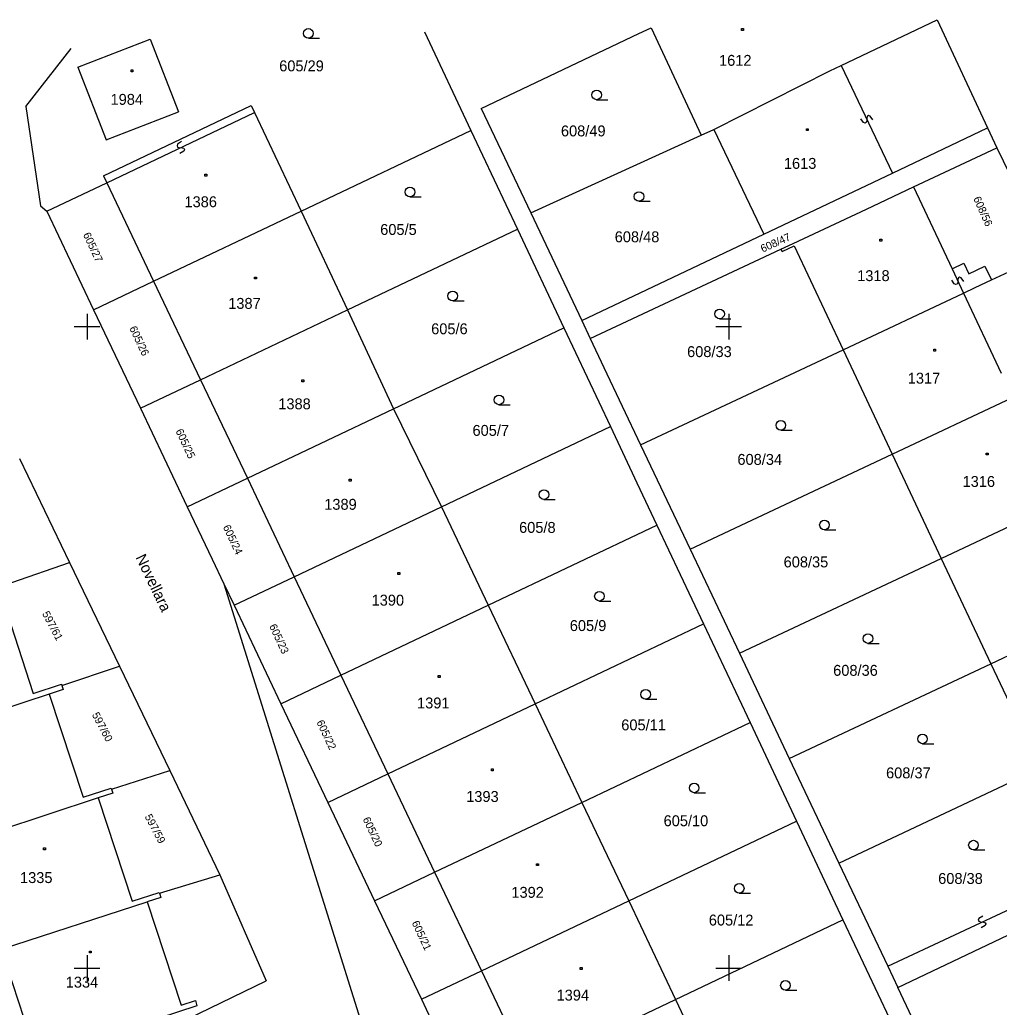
# Model space of a CAD drawing. Extents: x -493648 to -493033, y -1127718 to -1127026.
# Drawn here: x -493205.2 to -493128.9, y -1127103.1 to -1127026.1 of the extents above; entities that cross this region are included whole.
import ezdxf

# ---------------------------------------------------------------- set-up
doc = ezdxf.new("R2010")
doc.units = 0
doc.layers.add('katastrální mapa', color=7, linetype='Continuous')
doc.layers.add('síť', color=7, linetype='Continuous')

msp = doc.modelspace()

# ---------------------------------------------------------------- linework, layer by layer
at = {"layer": 'katastrální mapa'}
for p, q in [((-493141.24, -1127029.66), (-493133.78, -1127026.09)), ((-493133.78, -1127026.09), (-493129.84, -1127034.51)), ((-493157, -1127027.17), (-493156.05, -1127026.71)), ((-493156.05, -1127026.71), (-493152.15, -1127035.09)), ((-493149.02, -1127026.77), (-493148.87, -1127026.77)), ((-493149.02, -1127026.92), (-493149.02, -1127026.77)), ((-493148.87, -1127026.77), (-493148.87, -1127026.92)), ((-493200.73, -1127029.79), (-493195.09, -1127027.6)), ((-493195.09, -1127027.6), (-493192.87, -1127033.26)), ((-493182.76, -1127027.53), (-493181.88, -1127027.53)), ((-493173.71, -1127027.03), (-493170.09, -1127034.72)), ((-493169.29, -1127033.01), (-493157, -1127027.17)), ((-493148.87, -1127026.92), (-493149.02, -1127026.92)), ((-493204.77, -1127032.86), (-493201.25, -1127028.34)), ((-493200.73, -1127029.79), (-493198.5, -1127035.44)), ((-493142.14, -1127030.06), (-493141.24, -1127029.66)), ((-493141.24, -1127029.66), (-493137.26, -1127038.04)), ((-493196.57, -1127030), (-493196.42, -1127030)), ((-493196.57, -1127030.15), (-493196.57, -1127030)), ((-493196.42, -1127030.15), (-493196.57, -1127030.15)), ((-493196.42, -1127030), (-493196.42, -1127030.15)), ((-493151.17, -1127034.64), (-493142.14, -1127030.06)), ((-493204.77, -1127032.86), (-493203.62, -1127040.6)), ((-493198.72, -1127038.25), (-493187.21, -1127032.77)), ((-493187.21, -1127032.77), (-493186.95, -1127033.32)), ((-493169.29, -1127033.01), (-493165.43, -1127041.14)), ((-493160.3, -1127032.32), (-493159.42, -1127032.32)), ((-493198.5, -1127035.44), (-493192.87, -1127033.26)), ((-493198.46, -1127038.79), (-493186.95, -1127033.32)), ((-493186.95, -1127033.32), (-493183.32, -1127041.01)), ((-493139.2, -1127033.6), (-493139.25, -1127033.74)), ((-493139.25, -1127033.74), (-493139.25, -1127033.96)), ((-493139.11, -1127033.56), (-493139.2, -1127033.6)), ((-493138.98, -1127033.61), (-493139.11, -1127033.56)), ((-493138.78, -1127033.9), (-493138.98, -1127033.61)), ((-493139.52, -1127034.09), (-493139.72, -1127033.8)), ((-493139.39, -1127034.14), (-493139.52, -1127034.09)), ((-493139.3, -1127034.1), (-493139.39, -1127034.14)), ((-493139.25, -1127033.96), (-493139.3, -1127034.1)), ((-493137.26, -1127038.04), (-493129.84, -1127034.51)), ((-493129.84, -1127034.51), (-493129.11, -1127036.07)), ((-493183.32, -1127041.01), (-493170.09, -1127034.72)), ((-493170.09, -1127034.72), (-493166.47, -1127042.41)), ((-493165.43, -1127041.14), (-493152.15, -1127035.09)), ((-493152.15, -1127035.09), (-493151.17, -1127034.64)), ((-493151.17, -1127034.64), (-493147.28, -1127042.81)), ((-493143.96, -1127034.58), (-493143.81, -1127034.58)), ((-493143.96, -1127034.73), (-493143.96, -1127034.58)), ((-493143.81, -1127034.73), (-493143.96, -1127034.73)), ((-493143.81, -1127034.58), (-493143.81, -1127034.73)), ((-493192.95, -1127035.78), (-493192.99, -1127035.92)), ((-493192.99, -1127035.92), (-493192.95, -1127036.01)), ((-493192.65, -1127035.59), (-493192.95, -1127035.78)), ((-493192.95, -1127036.01), (-493192.82, -1127036.05)), ((-493192.82, -1127036.05), (-493192.59, -1127036.06)), ((-493192.59, -1127036.06), (-493192.46, -1127036.1)), ((-493192.46, -1127036.1), (-493192.42, -1127036.19)), ((-493135.61, -1127039.12), (-493129.11, -1127036.07)), ((-493129.11, -1127036.07), (-493125.16, -1127044.31)), ((-493192.46, -1127036.33), (-493192.76, -1127036.52)), ((-493192.42, -1127036.19), (-493192.46, -1127036.33)), ((-493198.72, -1127038.25), (-493198.46, -1127038.79)), ((-493190.82, -1127038.13), (-493190.67, -1127038.13)), ((-493190.82, -1127038.28), (-493190.82, -1127038.13)), ((-493190.67, -1127038.28), (-493190.82, -1127038.28)), ((-493190.67, -1127038.13), (-493190.67, -1127038.28)), ((-493147.28, -1127042.81), (-493137.26, -1127038.04)), ((-493203.14, -1127041.01), (-493198.46, -1127038.79)), ((-493198.46, -1127038.79), (-493194.81, -1127046.47)), ((-493139.28, -1127040.84), (-493135.61, -1127039.12)), ((-493135.61, -1127039.12), (-493132.61, -1127045.5)), ((-493174.84, -1127039.89), (-493173.96, -1127039.89)), ((-493203.62, -1127040.6), (-493203.14, -1127041.01)), ((-493157, -1127040.24), (-493156.12, -1127040.24)), ((-493203.14, -1127041.01), (-493199.49, -1127048.69)), ((-493194.81, -1127046.47), (-493183.32, -1127041.01)), ((-493183.32, -1127041.01), (-493179.7, -1127048.7)), ((-493165.43, -1127041.14), (-493161.45, -1127049.54)), ((-493145, -1127043.53), (-493139.28, -1127040.84)), ((-493179.7, -1127048.7), (-493166.47, -1127042.41)), ((-493166.47, -1127042.41), (-493162.85, -1127050.1)), ((-493161.45, -1127049.54), (-493147.28, -1127042.81)), ((-493145.94, -1127043.97), (-493145, -1127043.53)), ((-493145.85, -1127044.16), (-493144.91, -1127043.71)), ((-493144.91, -1127043.71), (-493141.1, -1127051.81)), ((-493138.23, -1127043.19), (-493138.08, -1127043.19)), ((-493138.23, -1127043.34), (-493138.23, -1127043.19)), ((-493138.08, -1127043.34), (-493138.23, -1127043.34)), ((-493138.08, -1127043.19), (-493138.08, -1127043.34)), ((-493160.79, -1127050.94), (-493145.94, -1127043.97)), ((-493145.94, -1127043.97), (-493145.85, -1127044.16)), ((-493129.54, -1127046.37), (-493125.16, -1127044.31)), ((-493132.61, -1127045.5), (-493131.69, -1127045.07)), ((-493131.69, -1127045.07), (-493131.31, -1127045.88)), ((-493131.31, -1127045.88), (-493130.05, -1127045.29)), ((-493130.05, -1127045.29), (-493129.54, -1127046.37)), ((-493132.61, -1127045.5), (-493131.72, -1127047.39)), ((-493199.49, -1127048.69), (-493194.81, -1127046.47)), ((-493194.81, -1127046.47), (-493191.16, -1127054.14)), ((-493186.95, -1127046.14), (-493186.8, -1127046.14)), ((-493186.95, -1127046.29), (-493186.95, -1127046.14)), ((-493186.8, -1127046.29), (-493186.95, -1127046.29)), ((-493186.8, -1127046.14), (-493186.8, -1127046.29)), ((-493132.44, -1127046.68), (-493132.63, -1127046.39)), ((-493132.31, -1127046.73), (-493132.44, -1127046.68)), ((-493132.22, -1127046.69), (-493132.31, -1127046.73)), ((-493132.17, -1127046.56), (-493132.22, -1127046.69)), ((-493132.16, -1127046.33), (-493132.17, -1127046.56)), ((-493132.11, -1127046.2), (-493132.16, -1127046.33)), ((-493132.02, -1127046.16), (-493132.11, -1127046.2)), ((-493131.89, -1127046.21), (-493132.02, -1127046.16)), ((-493131.7, -1127046.5), (-493131.89, -1127046.21)), ((-493130.8, -1127046.96), (-493129.54, -1127046.37)), ((-493141.1, -1127051.81), (-493131.72, -1127047.39)), ((-493131.72, -1127047.39), (-493130.8, -1127046.96)), ((-493131.72, -1127047.39), (-493128.77, -1127053.64)), ((-493171.51, -1127047.99), (-493170.63, -1127047.99)), ((-493199.49, -1127048.69), (-493195.84, -1127056.37)), ((-493191.16, -1127054.14), (-493179.7, -1127048.7)), ((-493179.7, -1127048.7), (-493176.12, -1127056.41)), ((-493161.45, -1127049.54), (-493160.79, -1127050.94)), ((-493150.72, -1127049.39), (-493149.84, -1127049.39)), ((-493176.12, -1127056.41), (-493162.85, -1127050.1)), ((-493162.85, -1127050.1), (-493159.23, -1127057.79)), ((-493160.79, -1127050.94), (-493159.73, -1127053.19)), ((-493156.87, -1127059.23), (-493141.1, -1127051.81)), ((-493141.1, -1127051.81), (-493137.27, -1127059.94)), ((-493134.04, -1127051.76), (-493133.89, -1127051.76)), ((-493134.04, -1127051.91), (-493134.04, -1127051.76)), ((-493133.89, -1127051.91), (-493134.04, -1127051.91)), ((-493133.89, -1127051.76), (-493133.89, -1127051.91)), ((-493159.73, -1127053.19), (-493156.87, -1127059.23)), ((-493195.84, -1127056.37), (-493191.16, -1127054.14)), ((-493191.16, -1127054.14), (-493187.51, -1127061.82)), ((-493183.26, -1127054.15), (-493183.11, -1127054.15)), ((-493183.26, -1127054.3), (-493183.26, -1127054.15)), ((-493183.11, -1127054.3), (-493183.26, -1127054.3)), ((-493183.11, -1127054.15), (-493183.11, -1127054.3)), ((-493167.91, -1127056.09), (-493167.03, -1127056.09)), ((-493137.27, -1127059.94), (-493127.89, -1127055.53)), ((-493195.84, -1127056.37), (-493192.19, -1127064.04)), ((-493187.51, -1127061.82), (-493176.12, -1127056.41)), ((-493176.12, -1127056.41), (-493172.39, -1127064.05)), ((-493172.39, -1127064.05), (-493159.23, -1127057.79)), ((-493159.23, -1127057.79), (-493157.16, -1127062.17)), ((-493145.95, -1127058.07), (-493145.07, -1127058.07)), ((-493156.87, -1127059.23), (-493153.02, -1127067.35)), ((-493153.02, -1127067.35), (-493137.27, -1127059.94)), ((-493137.27, -1127059.94), (-493133.45, -1127068.07)), ((-493129.95, -1127059.86), (-493129.8, -1127059.86)), ((-493129.95, -1127060.01), (-493129.95, -1127059.86)), ((-493129.8, -1127059.86), (-493129.8, -1127060.01)), ((-493205.26, -1127060.28), (-493201.38, -1127068.38)), ((-493129.8, -1127060.01), (-493129.95, -1127060.01)), ((-493192.19, -1127064.04), (-493187.51, -1127061.82)), ((-493187.51, -1127061.82), (-493183.87, -1127069.5)), ((-493179.57, -1127061.89), (-493179.42, -1127061.89)), ((-493179.57, -1127062.04), (-493179.57, -1127061.89)), ((-493179.42, -1127062.04), (-493179.57, -1127062.04)), ((-493179.42, -1127061.89), (-493179.42, -1127062.04)), ((-493157.16, -1127062.17), (-493155.6, -1127065.48)), ((-493164.4, -1127063.47), (-493163.52, -1127063.47)), ((-493133.45, -1127068.07), (-493124.06, -1127063.66)), ((-493192.19, -1127064.04), (-493190.25, -1127068.13)), ((-493183.87, -1127069.5), (-493172.39, -1127064.05)), ((-493172.39, -1127064.05), (-493168.74, -1127071.72)), ((-493168.74, -1127071.72), (-493155.6, -1127065.48)), ((-493155.6, -1127065.48), (-493151.98, -1127073.17)), ((-493142.55, -1127065.84), (-493141.67, -1127065.84)), ((-493153.02, -1127067.35), (-493149.17, -1127075.46)), ((-493205.86, -1127069.94), (-493201.38, -1127068.38)), ((-493201.38, -1127068.38), (-493197.47, -1127076.47)), ((-493190.25, -1127068.13), (-493189.34, -1127070.04)), ((-493149.17, -1127075.46), (-493133.45, -1127068.07)), ((-493133.45, -1127068.07), (-493129.58, -1127076.28)), ((-493175.79, -1127069.18), (-493175.64, -1127069.18)), ((-493175.79, -1127069.33), (-493175.79, -1127069.18)), ((-493175.64, -1127069.18), (-493175.64, -1127069.33)), ((-493188.54, -1127071.72), (-493183.87, -1127069.5)), ((-493183.87, -1127069.5), (-493180.22, -1127077.18)), ((-493175.64, -1127069.33), (-493175.79, -1127069.33)), ((-493189.34, -1127070.04), (-493188.54, -1127071.72)), ((-493189.34, -1127070.04), (-493167.78, -1127138.87)), ((-493160.08, -1127071.39), (-493159.2, -1127071.39)), ((-493188.54, -1127071.72), (-493184.9, -1127079.4)), ((-493180.22, -1127077.18), (-493168.74, -1127071.72)), ((-493168.74, -1127071.72), (-493165.09, -1127079.4)), ((-493129.58, -1127076.28), (-493120.2, -1127071.87)), ((-493165.09, -1127079.4), (-493151.98, -1127073.17)), ((-493151.98, -1127073.17), (-493148.35, -1127080.86)), ((-493139.16, -1127074.69), (-493138.28, -1127074.69)), ((-493149.17, -1127075.46), (-493145.29, -1127083.66)), ((-493201.97, -1127077.97), (-493197.47, -1127076.47)), ((-493197.47, -1127076.47), (-493193.55, -1127084.6)), ((-493145.29, -1127083.66), (-493129.58, -1127076.28)), ((-493129.58, -1127076.28), (-493125.76, -1127084.43)), ((-493184.9, -1127079.4), (-493180.22, -1127077.18)), ((-493180.22, -1127077.18), (-493176.57, -1127084.85)), ((-493172.64, -1127077.19), (-493172.49, -1127077.19)), ((-493172.64, -1127077.34), (-493172.64, -1127077.19)), ((-493172.49, -1127077.34), (-493172.64, -1127077.34)), ((-493172.49, -1127077.19), (-493172.49, -1127077.34)), ((-493202, -1127077.88), (-493201.97, -1127077.97)), ((-493202.95, -1127078.64), (-493214.24, -1127082.36)), ((-493156.48, -1127079.04), (-493155.6, -1127079.04)), ((-493184.9, -1127079.4), (-493181.25, -1127087.08)), ((-493176.57, -1127084.85), (-493165.09, -1127079.4)), ((-493165.09, -1127079.4), (-493161.45, -1127087.08)), ((-493161.45, -1127087.08), (-493148.35, -1127080.86)), ((-493148.35, -1127080.86), (-493144.73, -1127088.55)), ((-493134.91, -1127082.51), (-493134.03, -1127082.51)), ((-493145.29, -1127083.66), (-493141.43, -1127091.81)), ((-493168.5, -1127084.48), (-493168.35, -1127084.48)), ((-493168.5, -1127084.63), (-493168.5, -1127084.48)), ((-493168.35, -1127084.48), (-493168.35, -1127084.63)), ((-493141.43, -1127091.81), (-493125.76, -1127084.43)), ((-493198.1, -1127086.05), (-493193.55, -1127084.6)), ((-493193.55, -1127084.6), (-493189.66, -1127092.72)), ((-493181.25, -1127087.08), (-493176.57, -1127084.85)), ((-493176.57, -1127084.85), (-493172.93, -1127092.53)), ((-493168.35, -1127084.63), (-493168.5, -1127084.63)), ((-493198.12, -1127085.98), (-493198.1, -1127086.05)), ((-493199.13, -1127086.74), (-493210.39, -1127090.45)), ((-493199.13, -1127086.74), (-493196.49, -1127094.79)), ((-493152.7, -1127086.33), (-493151.82, -1127086.33)), ((-493136.84, -1127101.5), (-493105.21, -1127086.48)), ((-493181.25, -1127087.08), (-493177.6, -1127094.75)), ((-493172.93, -1127092.53), (-493161.45, -1127087.08)), ((-493161.45, -1127087.08), (-493157.8, -1127094.75)), ((-493157.8, -1127094.75), (-493144.73, -1127088.55)), ((-493144.73, -1127088.55), (-493141.11, -1127096.24)), ((-493203.39, -1127090.62), (-493203.24, -1127090.62)), ((-493203.39, -1127090.77), (-493203.39, -1127090.62)), ((-493203.24, -1127090.62), (-493203.24, -1127090.77)), ((-493203.24, -1127090.77), (-493203.39, -1127090.77)), ((-493130.94, -1127090.79), (-493130.06, -1127090.79)), ((-493164.99, -1127091.86), (-493164.84, -1127091.86)), ((-493164.99, -1127092.01), (-493164.99, -1127091.86)), ((-493164.84, -1127092.01), (-493164.99, -1127092.01)), ((-493164.84, -1127091.86), (-493164.84, -1127092.01)), ((-493141.43, -1127091.81), (-493137.62, -1127099.85)), ((-493194.35, -1127094.15), (-493189.66, -1127092.72)), ((-493189.66, -1127092.72), (-493186.04, -1127100.98)), ((-493177.6, -1127094.75), (-493172.93, -1127092.53)), ((-493172.93, -1127092.53), (-493169.28, -1127100.21)), ((-493137.62, -1127099.85), (-493122.94, -1127092.96)), ((-493149.19, -1127094.16), (-493148.31, -1127094.16)), ((-493206.67, -1127098.53), (-493195.31, -1127094.84)), ((-493195.31, -1127094.84), (-493192.66, -1127102.89)), ((-493177.6, -1127094.75), (-493173.95, -1127102.43)), ((-493169.28, -1127100.21), (-493157.8, -1127094.75)), ((-493157.8, -1127094.75), (-493154.16, -1127102.44)), ((-493130.52, -1127096.13), (-493130.57, -1127096.26)), ((-493130.22, -1127095.94), (-493130.52, -1127096.13)), ((-493154.16, -1127102.44), (-493141.11, -1127096.24)), ((-493141.11, -1127096.24), (-493137.49, -1127103.93)), ((-493130.57, -1127096.26), (-493130.52, -1127096.35)), ((-493130.52, -1127096.35), (-493130.39, -1127096.4)), ((-493130.39, -1127096.4), (-493130.17, -1127096.41)), ((-493130.04, -1127096.68), (-493130.34, -1127096.87)), ((-493130.17, -1127096.41), (-493130.04, -1127096.46)), ((-493130.04, -1127096.46), (-493129.99, -1127096.55)), ((-493129.99, -1127096.55), (-493130.04, -1127096.68)), ((-493199.82, -1127098.67), (-493199.67, -1127098.67)), ((-493199.82, -1127098.82), (-493199.82, -1127098.67)), ((-493199.67, -1127098.82), (-493199.82, -1127098.82)), ((-493199.67, -1127098.67), (-493199.67, -1127098.82)), ((-493161.57, -1127099.96), (-493161.42, -1127099.96)), ((-493161.57, -1127100.11), (-493161.57, -1127099.96)), ((-493161.42, -1127099.96), (-493161.42, -1127100.11)), ((-493137.62, -1127099.85), (-493136.84, -1127101.5)), ((-493173.95, -1127102.43), (-493169.28, -1127100.21)), ((-493169.28, -1127100.21), (-493165.63, -1127107.89)), ((-493161.42, -1127100.11), (-493161.57, -1127100.11)), ((-493220.46, -1127117.66), (-493186.04, -1127100.98)), ((-493132.35, -1127110.95), (-493136.84, -1127101.5)), ((-493145.59, -1127101.72), (-493144.71, -1127101.72)), ((-493192.66, -1127102.89), (-493191.56, -1127102.53)), ((-493173.95, -1127102.43), (-493170.3, -1127110.11)), ((-493165.63, -1127107.89), (-493154.16, -1127102.44)), ((-493154.16, -1127102.44), (-493150.51, -1127110.12))]:
    msp.add_line(p, q, dxfattribs=at)
for points in [[(-493206.83, -1127070.57), (-493204.19, -1127078.61), (-493202, -1127077.88)], [(-493201.97, -1127077.97), (-493201.87, -1127078.28), (-493202.95, -1127078.64)], [(-493202.95, -1127078.64), (-493200.3, -1127086.69), (-493198.12, -1127085.98)], [(-493198.1, -1127086.05), (-493197.99, -1127086.37), (-493199.13, -1127086.74)], [(-493196.49, -1127094.79), (-493194.37, -1127094.1), (-493194.35, -1127094.15)], [(-493194.35, -1127094.15), (-493194.24, -1127094.49), (-493195.31, -1127094.84)], [(-493205.05, -1127106.97), (-493204.01, -1127106.62), (-493206.67, -1127098.53)], [(-493191.56, -1127102.53), (-493191.45, -1127102.93), (-493204.92, -1127107.35), (-493205.05, -1127106.97)]]:
    msp.add_lwpolyline(points, dxfattribs=at)
for centre in [(-493182.76, -1127027.155), (-493160.3, -1127031.945), (-493174.84, -1127039.515), (-493157, -1127039.865), (-493171.51, -1127047.615), (-493150.72, -1127049.015), (-493167.91, -1127055.715), (-493145.95, -1127057.695), (-493164.4, -1127063.095), (-493142.55, -1127065.465), (-493160.08, -1127071.015), (-493139.16, -1127074.315), (-493156.48, -1127078.665), (-493134.91, -1127082.135), (-493152.7, -1127085.955), (-493130.94, -1127090.415), (-493149.19, -1127093.785), (-493145.59, -1127101.345)]:
    msp.add_circle(centre, 0.375, dxfattribs=at)
at = {"layer": 'síť'}
for p, q in [((-493200, -1127049), (-493200, -1127051)), ((-493150, -1127049), (-493150, -1127051)), ((-493201, -1127050), (-493199, -1127050)), ((-493151, -1127050), (-493149, -1127050)), ((-493200, -1127099), (-493200, -1127101)), ((-493150, -1127099), (-493150, -1127101)), ((-493201, -1127100), (-493199, -1127100)), ((-493151, -1127100), (-493149, -1127100))]:
    msp.add_line(p, q, dxfattribs=at)

# ---------------------------------------------------------------- texts
at = {"layer": 'katastrální mapa'}
for s, p in [('1612', (-493150.76, -1127029.68)), ('605/29', (-493185.03, -1127030.11)), ('1984', (-493198.17, -1127032.72)), ('608/49', (-493163.08, -1127035.18)), ('1613', (-493145.71, -1127037.71)), ('1386', (-493192.41, -1127040.7)), ('605/5', (-493177.16, -1127042.86)), ('608/48', (-493158.89, -1127043.43)), ('1318', (-493140, -1127046.46)), ('1387', (-493189, -1127048.62)), ('605/6', (-493173.19, -1127050.6)), ('608/33', (-493153.25, -1127052.38)), ('1317', (-493136.06, -1127054.45)), ('1388', (-493185.1, -1127056.45)), ('605/7', (-493169.97, -1127058.52)), ('608/34', (-493149.33, -1127060.78)), ('1316', (-493131.79, -1127062.5)), ('1389', (-493181.52, -1127064.28)), ('605/8', (-493166.34, -1127066.08)), ('608/35', (-493145.73, -1127068.77)), ('1390', (-493177.83, -1127071.75)), ('605/9', (-493162.39, -1127073.73)), ('608/36', (-493141.87, -1127077.22)), ('1391', (-493174.29, -1127079.76)), ('605/11', (-493158.38, -1127081.47)), ('608/37', (-493137.75, -1127085.21)), ('1393', (-493170.46, -1127087.05)), ('605/10', (-493155.08, -1127088.94)), ('1335', (-493205.22, -1127093.37)), ('608/38', (-493133.69, -1127093.44)), ('1392', (-493166.94, -1127094.52)), ('605/12', (-493151.56, -1127096.68)), ('1334', (-493201.66, -1127101.52)), ('1394', (-493163.42, -1127102.53))]:
    msp.add_text(s, height=0.849996, dxfattribs=at).set_placement(p)
for s, height, rotation, p in [('608/56', 0.599994, 293.9849972, (-493130.97, -1127040.02)), ('605/27', 0.599994, 295.1279972, (-493200.33, -1127042.83)), ('608/47', 0.599994, 24.1199972, (-493147.36, -1127044.24)), ('605/26', 0.599994, 295.1279972, (-493196.72, -1127050.13)), ('605/25', 0.599994, 295.1279972, (-493193.12, -1127058.14)), ('605/24', 0.599994, 295.1279972, (-493189.43, -1127065.62)), ('Novellara', 0.849996, 295.5893389, (-493196.24, -1127067.99)), ('597/61', 0.599994, 297.765, (-493203.52, -1127072.37)), ('605/23', 0.599994, 295.1279972, (-493185.83, -1127073.35)), ('597/60', 0.599994, 297.765, (-493199.64, -1127080.25)), ('605/22', 0.599994, 295.1279972, (-493182.14, -1127080.83)), ('597/59', 0.599994, 297.765, (-493195.53, -1127088.19)), ('605/20', 0.599994, 295.1279972, (-493178.54, -1127088.39)), ('605/21', 0.599994, 295.1279972, (-493174.72, -1127096.47))]:
    msp.add_text(s, height=height, rotation=rotation, dxfattribs=at).set_placement(p)

doc.saveas('drawing.dxf')
